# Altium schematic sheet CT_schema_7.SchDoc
size 274 x 160 mm
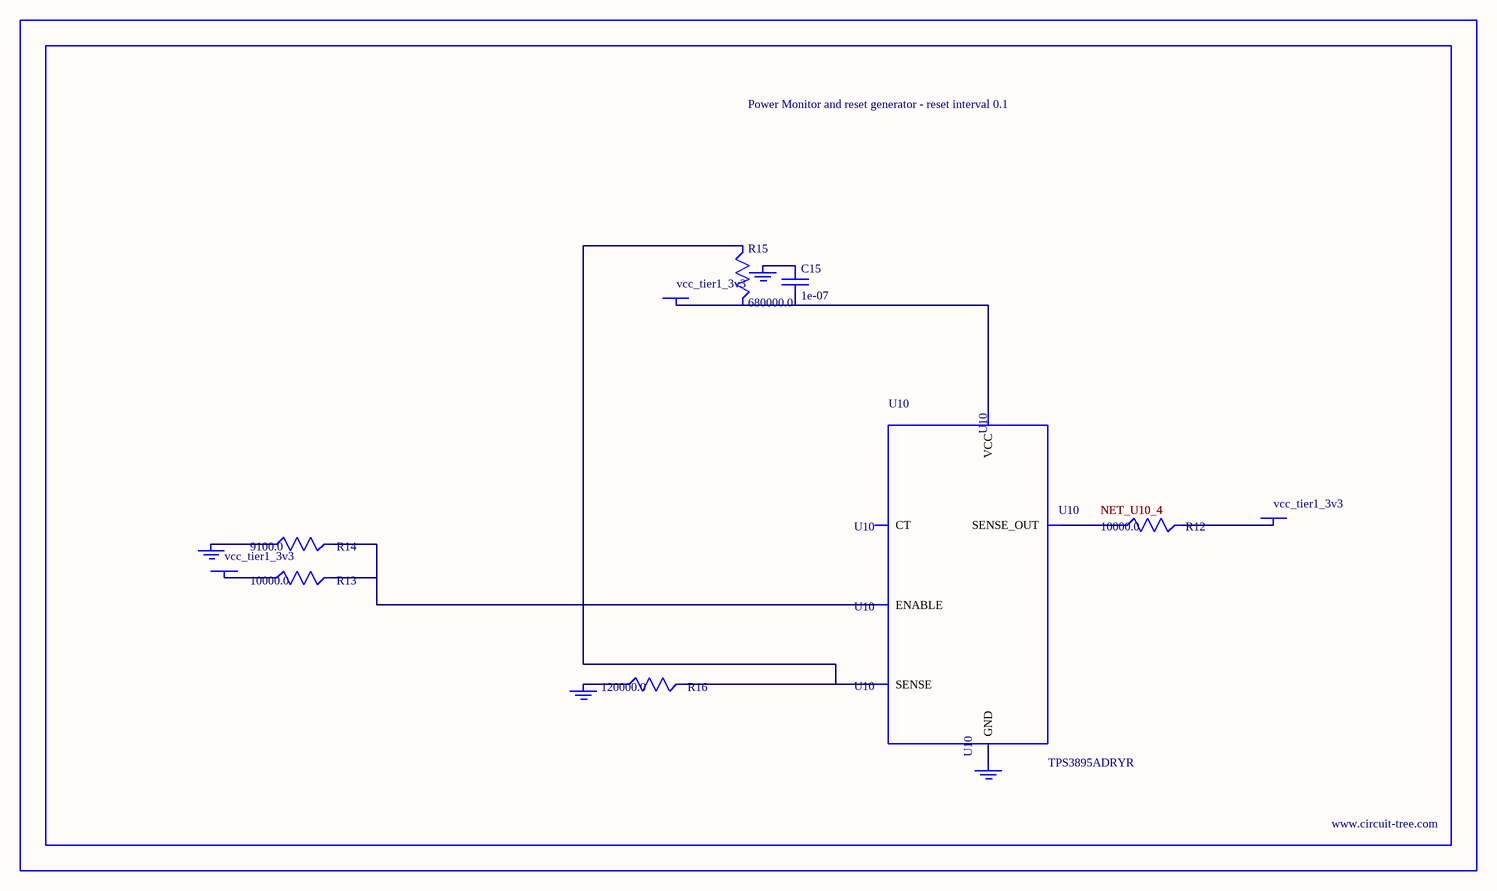
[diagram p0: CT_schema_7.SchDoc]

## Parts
BORDER6  (no value)
C15  1e-07  [C0402]
GND_INSTANCE_6_0  (no value)
GND_INSTANCE_6_1  (no value)
GND_INSTANCE_6_2  (no value)
GND_INSTANCE_6_3  (no value)
POWER_INSTANCE_6_0  vcc_tier1_3v3
POWER_INSTANCE_6_1  vcc_tier1_3v3
POWER_INSTANCE_6_2  vcc_tier1_3v3
R12  10000.0  [R0603]
R13  10000.0  [R0603]
R14  9100.0  [R0603]
R15  680000.0  [R0603]
R16  120000.0  [R0603]
U10  TPS3895ADRYR  [SON-6]

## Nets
NetC15_1: C15.1 GND_INSTANCE_6_2.0(GND)
NetC15_2: C15.2 POWER_INSTANCE_6_2.0(PWR) R15.2 U10.6(VCC)
NetGND_INSTANCE_6_0_0: GND_INSTANCE_6_0.0(GND) R14.1
NetGND_INSTANCE_6_1_0: GND_INSTANCE_6_1.0(GND) R16.1
NetGND_INSTANCE_6_3_0: GND_INSTANCE_6_3.0(GND) U10.2(GND)
NetPOWER_INSTANCE_6_0_0: POWER_INSTANCE_6_0.0(PWR) R13.1
NetPOWER_INSTANCE_6_1_0: POWER_INSTANCE_6_1.0(PWR) R12.2
NetR12_1: R12.1 U10.4(SENSE_OUT)
NetR13_2: R13.2 R14.2 U10.1(ENABLE)
NetR15_1: R15.1 R16.2 U10.3(SENSE)

Not connected (* = marked no-connect by the designer): U10 5(CT)

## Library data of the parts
BORDER6 = BORDER_PAGE6
C15 = C0402C104K3RACTU
GND_INSTANCE_6_0-GND_INSTANCE_6_3 = GND
POWER_INSTANCE_6_0-POWER_INSTANCE_6_2 = PWR
R12 R13 = RC0603JR-0710KL
R14 = RC0603JR-079K1L
R15 = RC0603JR-07680KL
R16 = RC0603JR-07120KL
